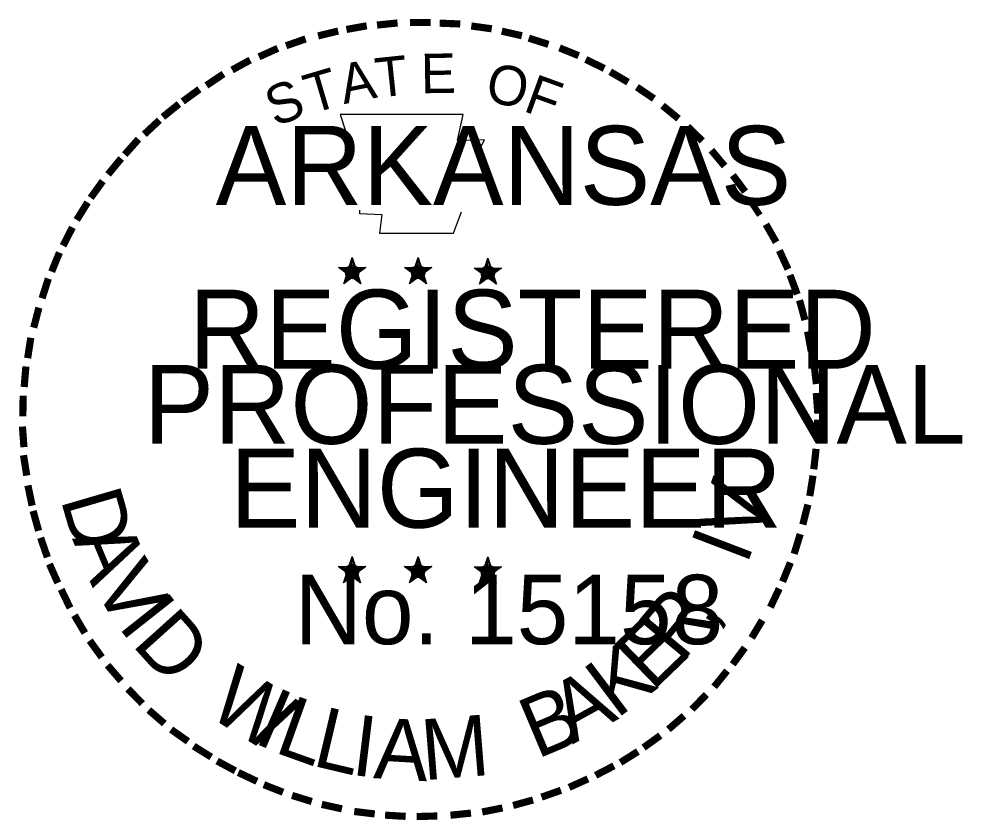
# Model space of a CAD drawing. Extents: x 34757 to 38214, y 51436 to 59430.
# Drawn here: x 36540.9 to 36662.7, y 56139 to 56242.6 of the extents above; entities that cross this region are included whole.
import ezdxf

# ---------------------------------------------------------------- set-up
doc = ezdxf.new("R2010")
doc.units = 0
doc.layers.add('R_Border PE', color=7, linetype='Continuous')
doc.layers.add('SHET_Stamp-PE-Chief-Eng', color=7, linetype='Continuous')

msp = doc.modelspace()

# ---------------------------------------------------------------- linework, layer by layer
at = {"layer": 'R_Border PE'}
for p, q in [((36583.98, 56211.72), (36583.77, 56210.43)), ((36583.98, 56209.86), (36583.98, 56211.72)), ((36583.98, 56211.72), (36584.23, 56210.45)), ((36592.5, 56211.72), (36592.29, 56210.43)), ((36592.5, 56209.86), (36592.5, 56211.72)), ((36592.5, 56211.72), (36592.75, 56210.45)), ((36601.49, 56211.66), (36601.28, 56210.37)), ((36601.49, 56209.8), (36601.49, 56211.66)), ((36601.49, 56211.66), (36601.74, 56210.38)), ((36582.2, 56210.42), (36583.98, 56209.86)), ((36582.2, 56210.42), (36583.49, 56210.2)), ((36582.2, 56210.42), (36583.41, 56209.8)), ((36585.75, 56210.42), (36583.98, 56209.86)), ((36585.75, 56210.42), (36584.29, 56210.17)), ((36585.75, 56210.42), (36584.71, 56209.9)), ((36590.72, 56210.42), (36592.5, 56209.86)), ((36590.72, 56210.42), (36592.01, 56210.2)), ((36590.72, 56210.42), (36591.93, 56209.8)), ((36594.27, 56210.42), (36592.5, 56209.86)), ((36594.27, 56210.42), (36592.81, 56210.17)), ((36594.27, 56210.42), (36593.23, 56209.9)), ((36599.71, 56210.36), (36601.49, 56209.8)), ((36599.71, 56210.36), (36601, 56210.13)), ((36599.71, 56210.36), (36600.92, 56209.74)), ((36603.26, 56210.36), (36601.49, 56209.8)), ((36603.26, 56210.36), (36601.8, 56210.11)), ((36603.26, 56210.36), (36602.22, 56209.84)), ((36582.88, 56208.34), (36583.98, 56209.86)), ((36582.88, 56208.34), (36583.52, 56209.59)), ((36582.88, 56208.34), (36583.97, 56209.45)), ((36585.07, 56208.34), (36583.97, 56209.44)), ((36585.07, 56208.34), (36583.98, 56209.86)), ((36585.07, 56208.34), (36584.37, 56209.83)), ((36591.39, 56208.34), (36592.5, 56209.86)), ((36591.39, 56208.34), (36592.04, 56209.59)), ((36591.39, 56208.34), (36592.49, 56209.45)), ((36593.58, 56208.34), (36592.49, 56209.44)), ((36593.58, 56208.34), (36592.5, 56209.86)), ((36593.58, 56208.34), (36592.88, 56209.83)), ((36600.39, 56208.28), (36601.49, 56209.8)), ((36600.39, 56208.28), (36601.03, 56209.53)), ((36600.39, 56208.28), (36601.48, 56209.39)), ((36602.58, 56208.28), (36601.48, 56209.37)), ((36602.58, 56208.28), (36601.49, 56209.8)), ((36602.58, 56208.28), (36601.88, 56209.77)), ((36583.96, 56173.1), (36583.75, 56171.81)), ((36583.96, 56171.24), (36583.96, 56173.1)), ((36583.96, 56173.1), (36584.21, 56171.82)), ((36592.47, 56173.1), (36592.26, 56171.81)), ((36592.47, 56171.24), (36592.47, 56173.1)), ((36592.47, 56173.1), (36592.72, 56171.82)), ((36601.48, 56173.05), (36601.27, 56171.76)), ((36601.48, 56171.19), (36601.48, 56173.05)), ((36601.48, 56173.05), (36601.73, 56171.77)), ((36582.18, 56171.8), (36583.96, 56171.24)), ((36582.18, 56171.8), (36583.47, 56171.57)), ((36582.18, 56171.8), (36583.39, 56171.18)), ((36582.86, 56169.72), (36583.96, 56171.24)), ((36585.73, 56171.8), (36583.96, 56171.24)), ((36585.05, 56169.72), (36583.96, 56171.24)), ((36585.73, 56171.8), (36584.27, 56171.55)), ((36585.05, 56169.72), (36584.35, 56171.21)), ((36585.73, 56171.8), (36584.69, 56171.28)), ((36590.69, 56171.8), (36592.47, 56171.24)), ((36590.69, 56171.8), (36591.98, 56171.57)), ((36590.69, 56171.8), (36591.9, 56171.18)), ((36591.37, 56169.72), (36592.47, 56171.24)), ((36594.24, 56171.8), (36592.47, 56171.24)), ((36593.56, 56169.72), (36592.47, 56171.24)), ((36594.24, 56171.8), (36592.78, 56171.55)), ((36593.56, 56169.72), (36592.86, 56171.21)), ((36594.24, 56171.8), (36593.2, 56171.28)), ((36599.7, 56171.75), (36601.48, 56171.19)), ((36599.7, 56171.75), (36600.99, 56171.52)), ((36599.7, 56171.75), (36600.91, 56171.13)), ((36600.38, 56169.67), (36601.48, 56171.19)), ((36603.25, 56171.75), (36601.48, 56171.19)), ((36602.57, 56169.67), (36601.48, 56171.19)), ((36603.25, 56171.75), (36601.79, 56171.5)), ((36602.57, 56169.67), (36601.87, 56171.16)), ((36603.25, 56171.75), (36602.21, 56171.23)), ((36582.86, 56169.72), (36583.5, 56170.97)), ((36582.86, 56169.72), (36583.95, 56170.83)), ((36585.05, 56169.72), (36583.95, 56170.81)), ((36591.37, 56169.72), (36592.01, 56170.97)), ((36591.37, 56169.72), (36592.46, 56170.83)), ((36593.56, 56169.72), (36592.46, 56170.81)), ((36600.38, 56169.67), (36601.02, 56170.92)), ((36600.38, 56169.67), (36601.47, 56170.78)), ((36602.57, 56169.67), (36601.47, 56170.76))]:
    msp.add_line(p, q, dxfattribs=at)
for points in [[(36582.41, 56230.2), (36583.78, 56225.98)], [(36600.31, 56225.5), (36601.04, 56226.95), (36597.55, 56226.83), (36598.3, 56230.2), (36582.41, 56230.2)], [(36584.92, 56217.84), (36584.92, 56217.4), (36587.79, 56217.3), (36587.51, 56214.89), (36597.05, 56214.89), (36598.08, 56217.63)], [(36592.5, 56211.72), (36593.58, 56208.34), (36590.72, 56210.42), (36594.27, 56210.42), (36591.39, 56208.34), (36592.5, 56211.72)], [(36601.49, 56211.66), (36602.58, 56208.28), (36599.71, 56210.36), (36603.26, 56210.36), (36600.39, 56208.28), (36601.49, 56211.66)], [(36583.96, 56173.1), (36585.05, 56169.72), (36582.18, 56171.8), (36585.73, 56171.8), (36582.86, 56169.72), (36583.96, 56173.1)], [(36592.47, 56173.1), (36593.56, 56169.72), (36590.69, 56171.8), (36594.24, 56171.8), (36591.37, 56169.72), (36592.47, 56173.1)], [(36601.48, 56173.05), (36602.57, 56169.67), (36599.7, 56171.75), (36603.25, 56171.75), (36600.38, 56169.67), (36601.48, 56173.05)]]:
    msp.add_lwpolyline(points, dxfattribs=at)
for centre, radius in [((36583.97, 56209.85), 0.878), ((36583.97, 56209.85), 0.737), ((36583.97, 56209.85), 0.59), ((36583.97, 56209.85), 0.505), ((36583.97, 56209.85), 0.381), ((36583.97, 56209.85), 0.253), ((36592.49, 56209.85), 0.878), ((36592.49, 56209.85), 0.737), ((36592.49, 56209.85), 0.59), ((36592.49, 56209.85), 0.505), ((36592.49, 56209.85), 0.381), ((36592.49, 56209.85), 0.253), ((36601.49, 56209.79), 0.878), ((36601.49, 56209.79), 0.737), ((36601.49, 56209.79), 0.59), ((36601.49, 56209.79), 0.505), ((36601.49, 56209.79), 0.381), ((36583.97, 56209.85), 0.151), ((36592.49, 56209.85), 0.151), ((36601.49, 56209.79), 0.253), ((36601.49, 56209.79), 0.151), ((36583.95, 56171.23), 0.878), ((36583.95, 56171.23), 0.737), ((36583.95, 56171.23), 0.59), ((36583.95, 56171.23), 0.505), ((36583.95, 56171.23), 0.381), ((36583.95, 56171.23), 0.253), ((36583.95, 56171.23), 0.151), ((36592.47, 56171.23), 0.878), ((36592.47, 56171.23), 0.737), ((36592.47, 56171.23), 0.59), ((36592.47, 56171.23), 0.505), ((36592.47, 56171.23), 0.381), ((36592.47, 56171.23), 0.253), ((36592.47, 56171.23), 0.151), ((36601.48, 56171.18), 0.878), ((36601.48, 56171.18), 0.737), ((36601.48, 56171.18), 0.59), ((36601.48, 56171.18), 0.505), ((36601.48, 56171.18), 0.381), ((36601.48, 56171.18), 0.253), ((36601.48, 56171.18), 0.151)]:
    msp.add_circle(centre, radius, dxfattribs=at)
at = {"layer": 'SHET_Stamp-PE-Chief-Eng'}
msp.add_lwpolyline([(36583.98, 56211.72), (36585.07, 56208.34), (36582.2, 56210.42), (36585.75, 56210.42), (36582.88, 56208.34), (36583.98, 56211.72)], dxfattribs=at)

# ---------------------------------------------------------------- texts
at = {"layer": 'R_Border PE'}
for s, height, rotation, p in [('-', 8.16, 10.2193, (36583.31, 56238)), ('-', 8.16, 5.8968, (36587.02, 56238.57)), ('-', 8.16, 0.1862, (36590.96, 56238.93)), ('-', 8.16, 357.743, (36594.65, 56238.87)), ('-', 8.16, 352.1617, (36598.44, 56238.58)), ('-', 8.16, 13.6302, (36579.85, 56237.18)), ('-', 8.16, 347.2049, (36602.11, 56238)), ('-', 8.16, 342.3362, (36605.35, 56237.21)), ('-', 8.16, 19.1761, (36576.02, 56235.95)), ('-', 8.16, 24.3072, (36572.79, 56234.58)), ('E', 5.1, 0.8323, (36592.86, 56232.94)), ('-', 8.16, 337.8551, (36609.1, 56236.07)), ('-', 8.16, 28.7918, (36569.56, 56232.96)), ('A', 5.1, 11.2132, (36582.89, 56231.53)), ('T', 5.1, 6.0228, (36587.22, 56232.37)), ('-', 8.16, 334.1211, (36612.31, 56234.69)), ('-', 8.16, 34.0636, (36566.52, 56231.07)), ('T', 5.1, 16.4036, (36578.68, 56230.25)), ('O', 5.1, 350.4515, (36601.04, 56231.86)), ('-', 8.16, 329.6409, (36615.27, 56233.25)), ('S', 5.1, 21.594, (36574.02, 56228.56)), ('F', 5.1, 340.0707, (36605.9, 56230.7)), ('-', 8.16, 36.2317, (36563.57, 56229.06)), ('-', 8.16, 325.8627, (36618.55, 56231.41)), ('-', 8.16, 38.9507, (36561.14, 56227.13)), ('-', 8.16, 320.5297, (36621.66, 56229.23)), ('-', 8.16, 42.9622, (36558.93, 56225.01)), ('-', 8.16, 315.5786, (36624.71, 56226.74)), ('-', 8.16, 48.4231, (36556.65, 56222.57)), ('-', 8.16, 309.8797, (36627.61, 56223.94)), ('-', 8.16, 50.6142, (36554.59, 56220.09)), ('-', 8.16, 306.6522, (36630.29, 56220.87)), ('-', 8.16, 54.2325, (36552.49, 56217.2)), ('-', 8.16, 58.0706, (36550.83, 56214.51)), ('-', 7.14, 303.6753, (36632.77, 56217.97)), ('-', 8.16, 299.6684, (36634.4, 56214.88)), ('-', 8.16, 62.8713, (36549.23, 56211.38)), ('-', 8.16, 67.7743, (36547.91, 56208.26)), ('-', 8.16, 294.6628, (36636.05, 56211.76)), ('-', 8.16, 72.3945, (36546.8, 56205.05)), ('-', 8.16, 290.5728, (36637.36, 56208.81)), ('-', 8.16, 75.461, (36545.79, 56201.41)), ('-', 8.16, 285.1233, (36638.55, 56205.86)), ('-', 8.16, 280.5493, (36639.57, 56202.07)), ('-', 8.16, 81.2013, (36545.12, 56197.77)), ('-', 8.16, 276.5962, (36640.4, 56198.15)), ('-', 8.16, 85.1863, (36544.73, 56194.25)), ('-', 8.16, 274.3301, (36640.7, 56194.47)), ('-', 8.16, 89.0622, (36544.6, 56190.67)), ('-', 8.16, 269.9407, (36640.88, 56191.25)), ('-', 8.16, 94.1959, (36544.78, 56186.98)), ('-', 8.16, 263.5172, (36640.78, 56187.85)), ('-', 8.16, 98.9479, (36545.15, 56183.57)), ('V', 7.85, 72.6573, (36636.01, 56174.62)), ('-', 8.16, 260.9953, (36640.42, 56184.52)), ('-', 8.16, 101.7149, (36545.84, 56179.84)), ('D', 7.85, 286.2848, (36546.29, 56180.54)), ('-', 8.16, 255.7626, (36639.86, 56181.06)), ('-', 8.16, 105.4578, (36546.66, 56176.8)), ('I', 7.85, 69.0301, (36634.87, 56171.87)), ('-', 8.16, 252.8681, (36638.94, 56177.39)), ('-', 8.16, 109.0874, (36547.76, 56173.58)), ('A', 7.85, 292.7835, (36547.78, 56175.43)), ('-', 8.16, 114.0643, (36549.05, 56170.54)), ('V', 7.85, 300.7936, (36550.4, 56169.42)), ('-', 8.16, 247.8887, (36637.8, 56173.96)), ('-', 8.16, 115.7289, (36550.61, 56167.39)), ('R', 7.85, 50.3651, (36626.46, 56159.18)), ('-', 8.16, 244.6197, (36636.46, 56170.75)), ('I', 7.85, 308.3502, (36553.62, 56164.13)), ('D', 7.85, 311.9774, (36555.41, 56161.75)), ('-', 8.16, 120.4471, (36552.43, 56164.4)), ('E', 7.85, 44.0175, (36622.71, 56155.57)), (',', 7.85, 57.4684, (36630.14, 56163.68)), ('-', 8.16, 239.0712, (36634.45, 56166.91)), ('-', 8.16, 125.8934, (36554.49, 56161.54)), ('K', 7.85, 36.9143, (36618.08, 56152.05)), ('-', 8.16, 233.8452, (36632.4, 56163.58)), ('-', 8.16, 130.7181, (36556.84, 56158.73)), ('W', 7.85, 328.0731, (36564.99, 56152.75)), ('-', 8.16, 231.2538, (36630.21, 56160.7)), ('A', 7.85, 28.9042, (36612.38, 56148.8)), ('-', 8.16, 134.2238, (36559.48, 56155.95)), ('I', 7.85, 336.6877, (36571.04, 56149.13)), ('B', 7.85, 22.8589, (36607.81, 56146.9)), ('-', 8.16, 225.7653, (36627.77, 56157.82)), ('L', 7.85, 340.3149, (36573.74, 56147.88)), ('-', 8.16, 138.9338, (36562.16, 56153.58)), ('L', 7.85, 346.6625, (36578.64, 56146.13)), ('-', 8.16, 221.0851, (36625.1, 56155.22)), ('I', 7.85, 353.0101, (36583.7, 56144.92)), ('A', 7.85, 356.6373, (36586.64, 56144.48)), ('M', 7.85, 4.6473, (36593.19, 56144.19)), ('-', 8.16, 144.6463, (36564.99, 56151.51)), ('-', 8.16, 215.7363, (36622.3, 56152.82)), ('-', 8.16, 148.0898, (36567.85, 56149.62)), ('-', 8.16, 212.2491, (36619.58, 56150.84)), ('-', 8.16, 151.5704, (36570.81, 56147.96)), ('-', 8.16, 154.6002, (36573.47, 56146.7)), ('-', 8.16, 207.3568, (36616.74, 56149.08)), ('-', 8.16, 204.2516, (36613.55, 56147.45)), ('-', 8.16, 158.5612, (36576.65, 56145.41)), ('-', 8.16, 199.4643, (36610.33, 56146.04)), ('-', 8.16, 162.7983, (36580.15, 56144.32)), ('-', 8.16, 195.4743, (36606.94, 56144.82)), ('-', 8.16, 167.5555, (36583.8, 56143.48)), ('-', 8.16, 191.2858, (36603.23, 56143.81)), ('-', 8.16, 173.1155, (36587.74, 56142.92)), ('-', 8.16, 176.5183, (36591.55, 56142.65)), ('-', 8.16, 181.5918, (36595.35, 56142.75)), ('-', 8.16, 185.8167, (36599.47, 56143.14))]:
    msp.add_text(s, height=height, rotation=rotation, dxfattribs=at).set_placement(p)
for s, height, p in [('ARKANSAS', 10.2, (36566.36, 56218.53)), ('REGISTERED', 10.2, (36562.9, 56197.37)), ('PROFESSIONAL', 10.1998, (36557.05, 56187.66)), ('ENGINEER', 10.2, (36568.2, 56176.83)), ('No. 15158', 8.961, (36576.57, 56161.78)), ('AAMU', 0.000102, (36592.13, 56144.16))]:
    msp.add_text(s, height=height, dxfattribs=at).set_placement(p)

doc.saveas('drawing.dxf')
